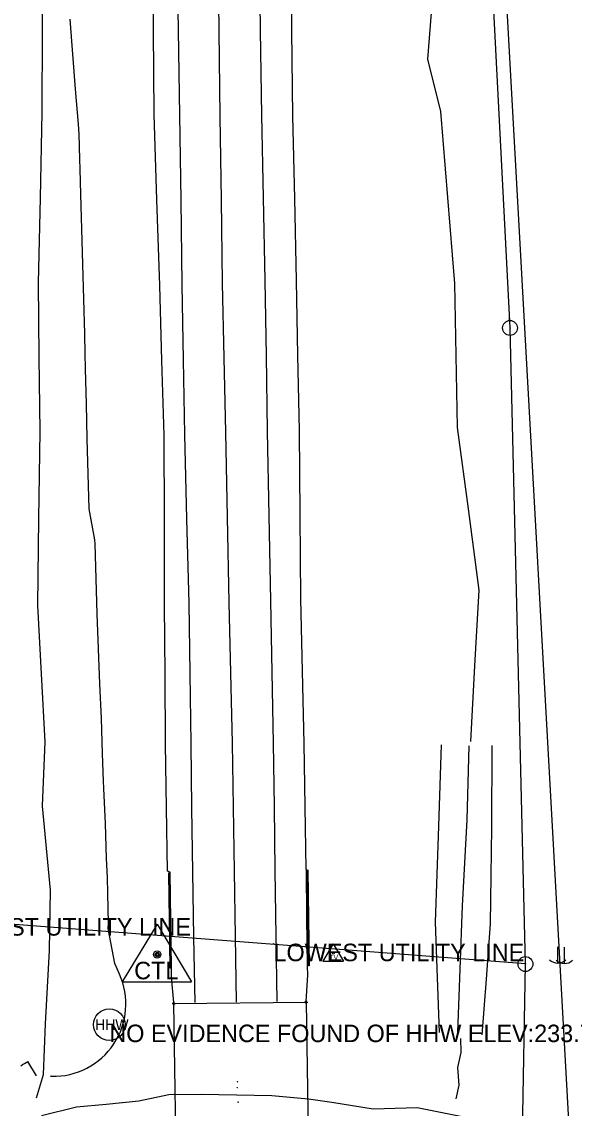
# Model space of a CAD drawing. Extents: x 1674300 to 1677920, y 225056 to 231852.
# Drawn here: x 1677397.6 to 1677555.6, y 229147 to 229457.6 of the extents above; entities that cross this region are included whole.
import ezdxf

# ---------------------------------------------------------------- set-up
doc = ezdxf.new("R2010")
doc.units = 0
for name, color, linetype in [('R_Proposed Const Limits_Cut', 7, 'Continuous'), ('R_Proposed Const Limits_Fill', 7, 'Continuous'), ('S_BRIDGE', 7, 'Continuous'), ('S_DITCHLINE', 7, 'Continuous'), ('S_EDGE_CONCRETE', 7, 'Continuous'), ('S_EDGE_PAVEMENT', 7, 'Continuous'), ('S_ELECTRIC_UTILITIES', 7, 'Continuous'), ('S_ELECTRIC_UTILITIES_ANNOT', 7, 'Continuous'), ('S_EXIST_ROW', 7, 'Continuous'), ('S_HIST_HIGH_WATER', 7, 'Continuous'), ('S_HIST_HIGH_WATER_ANNOT', 7, 'Continuous'), ('S_MSC_PT_SYM', 7, 'Continuous'), ('S_PAVEMENT_CROWN', 7, 'Continuous'), ('S_PRIMARY_CTL', 7, 'Continuous'), ('S_SECONDARY_CTL', 7, 'Continuous'), ('S_SHOULDER', 7, 'Continuous'), ('S_STR_PT_SYM', 7, 'Continuous'), ('S_STREAM', 7, 'Continuous'), ('S_UTILITY_POLE', 7, 'Continuous'), ('S_UTL_PT_SYM', 7, 'Continuous')]:
    doc.layers.add(name, color=color, linetype=linetype)

msp = doc.modelspace()

# ---------------------------------------------------------------- linework, layer by layer
at = {"layer": 'R_Proposed Const Limits_Cut'}
msp.add_lwpolyline([(1677397.4, 229159.19), (1677397.9, 229159.51), (1677398.39, 229159.82), (1677399.38, 229160.45)], dxfattribs=at)
at = {"layer": 'R_Proposed Const Limits_Fill'}
for p, q in [((1677401.84, 229156.28), (1677399.38, 229160.45)), ((1677406.18, 229156.17), (1677405.84, 229156.18))]:
    msp.add_line(p, q, dxfattribs=at)
msp.add_lwpolyline([(1677425.59, 229185.41), (1677424.21, 229188.45), (1677422.39, 229198.42), (1677422.41, 229199.98), (1677422.23, 229208.42), (1677422.12, 229212.97), (1677421.92, 229218.42), (1677421.54, 229228.42), (1677421.13, 229238.41), (1677421.04, 229240.56), (1677420.76, 229248.41), (1677420.41, 229258.4), (1677420.01, 229268.4), (1677419.61, 229278.39), (1677419.19, 229288.39), (1677418.88, 229298.38), (1677418.62, 229308.38), (1677418.58, 229309.52), (1677416.94, 229318.36), (1677416.67, 229328.36), (1677416.36, 229338.35), (1677416.12, 229348.35), (1677415.89, 229358.35), (1677415.78, 229362.8), (1677415.65, 229368.35), (1677415.39, 229378.34), (1677415.09, 229388.34), (1677414.81, 229398.34), (1677414.54, 229408.33), (1677414.35, 229415.48), (1677414.27, 229418.33), (1677414.07, 229425.48), (1677413.86, 229428.33), (1677413.04, 229438.32), (1677412.27, 229448.31), (1677411.5, 229458.3)], dxfattribs=at)
msp.add_arc((1677406.71, 229176.88), 20.71, 268.5476, 24.3154, dxfattribs=at)
at = {"layer": 'S_BRIDGE'}
for p, q in [((1677441.12, 229176.97), (1677478.98, 229177.38)), ((1677441.95, 229122.22), (1677441.12, 229176.97)), ((1677478.98, 229177.38), (1677479.86, 229122.68))]:
    msp.add_line(p, q, dxfattribs=at)
at = {"layer": 'S_DITCHLINE'}
for points in [[(1677401.81, 229150.07), (1677403.83, 229156.72), (1677404.42, 229171.13), (1677405.53, 229192.17), (1677405.88, 229209.42), (1677403.57, 229233.42), (1677404.29, 229251.75), (1677403.25, 229271.24), (1677402.21, 229290.73), (1677402.54, 229315.6), (1677402.86, 229340.46), (1677402.63, 229361.7), (1677402.41, 229382.95), (1677402.96, 229407.28), (1677403.51, 229431.62), (1677403.55, 229454.93), (1677403.6, 229478.23)], [(1677526.01, 229251.88), (1677527.22, 229273.51), (1677528.43, 229295.14), (1677525.35, 229318.39), (1677522.27, 229341.64), (1677521.88, 229362.2), (1677521.5, 229382.77), (1677519.49, 229407.37), (1677517.49, 229431.97), (1677513.78, 229446.92), (1677515.05, 229463.87)], [(1677525.45, 229250.61), (1677524.91, 229229.46), (1677523.57, 229204.88), (1677522.91, 229186.82), (1677522.26, 229168.76)]]:
    msp.add_lwpolyline(points, dxfattribs=at)
at = {"layer": 'S_EDGE_CONCRETE'}
for points in [[(1677517.07, 229168.73), (1677516.5, 229184.46), (1677515.92, 229200.19), (1677516.43, 229213.95), (1677516.93, 229227.7), (1677517.71, 229250.95)], [(1677529.33, 229168.07), (1677530.51, 229183.92), (1677531.7, 229199.76), (1677531.88, 229213.54), (1677532.07, 229227.32), (1677532.16, 229250.74)]]:
    msp.add_lwpolyline(points, dxfattribs=at)
for points in [[(1677439.61, 229214.28), (1677439.8, 229200.76), (1677439.99, 229187.23), (1677440.28, 229187.2), (1677440.08, 229200.79), (1677439.88, 229214.37)], [(1677479.45, 229215.12), (1677479.64, 229201.42), (1677479.83, 229187.73), (1677479.6, 229187.71), (1677479.42, 229201.44), (1677479.25, 229215.18)]]:
    msp.add_lwpolyline(points, close=True, dxfattribs=at)
at = {"layer": 'S_EDGE_PAVEMENT'}
for points in [[(1677447.19, 229177.27), (1677446.89, 229195.92), (1677446.59, 229214.57), (1677446.32, 229232.94), (1677446.04, 229251.31), (1677445.77, 229271.34), (1677445.49, 229291.37), (1677444.87, 229315.49), (1677444.24, 229339.62), (1677443.88, 229360.99), (1677443.52, 229382.36), (1677443.19, 229406.6), (1677442.86, 229430.84), (1677442.45, 229455.05), (1677442.04, 229479.26)], [(1677470.66, 229177.52), (1677470.39, 229196.28), (1677470.12, 229215.03), (1677469.88, 229233.21), (1677469.64, 229251.38), (1677469.24, 229271.73), (1677468.83, 229292.08), (1677468.37, 229316.34), (1677467.9, 229340.59), (1677467.59, 229362.11), (1677467.27, 229383.62), (1677466.77, 229407.23), (1677466.27, 229430.84), (1677465.93, 229455.12), (1677465.6, 229479.4)]]:
    msp.add_lwpolyline(points, dxfattribs=at)
at = {"layer": 'S_ELECTRIC_UTILITIES'}
for p, q in [((1677537.26, 229370.07), (1677525.77, 229595.69)), ((1677541.67, 229188.26), (1677537.26, 229370.07)), ((1677541.68, 229188.35), (1677278.13, 229208.63)), ((1677537.01, 228935.14), (1677541.67, 229188.26))]:
    msp.add_line(p, q, dxfattribs=at)
at = {"layer": 'S_EXIST_ROW'}
msp.add_line((1677555.5, 229117.02), (1677521.25, 229735.57), dxfattribs=at)
at = {"layer": 'S_HIST_HIGH_WATER'}
msp.add_circle((1677422.69, 229170.95), 4.5, dxfattribs=at)
at = {"layer": 'S_MSC_PT_SYM'}
for points in [[(1677469.62, 229194.08), (1677469.62, 229194.13), (1677469.62, 229194.08), (1677469.57, 229194.08), (1677469.62, 229194.08), (1677469.62, 229194.03), (1677469.62, 229194.08), (1677469.67, 229194.08)], [(1677459.3, 229154.61), (1677459.3, 229154.66), (1677459.3, 229154.61), (1677459.25, 229154.61), (1677459.3, 229154.61), (1677459.3, 229154.56), (1677459.3, 229154.61), (1677459.35, 229154.61)], [(1677459.27, 229153.01), (1677459.27, 229153.06), (1677459.27, 229153.01), (1677459.22, 229153.01), (1677459.27, 229153.01), (1677459.27, 229152.96), (1677459.27, 229153.01), (1677459.32, 229153.01)], [(1677459.52, 229148.81), (1677459.52, 229148.86), (1677459.52, 229148.81), (1677459.47, 229148.81), (1677459.52, 229148.81), (1677459.52, 229148.76), (1677459.52, 229148.81), (1677459.57, 229148.81)]]:
    msp.add_lwpolyline(points, dxfattribs=at)
at = {"layer": 'S_PAVEMENT_CROWN'}
msp.add_lwpolyline([(1677459.03, 229177.41), (1677458.76, 229196.1), (1677458.49, 229214.8), (1677458.18, 229233.1), (1677457.86, 229251.4), (1677457.39, 229271.52), (1677456.91, 229291.64), (1677456.47, 229315.95), (1677456.03, 229340.26), (1677455.53, 229361.57), (1677455.03, 229382.88), (1677454.71, 229406.68), (1677454.39, 229430.48), (1677454.11, 229454.96), (1677453.84, 229479.45)], dxfattribs=at)
at = {"layer": 'S_PRIMARY_CTL'}
for p, q in [((1677436.38, 229199.68), (1677426.35, 229183.17)), ((1677436.38, 229199.68), (1677446.2, 229183.17)), ((1677426.35, 229183.17), (1677446.2, 229183.17))]:
    msp.add_line(p, q, dxfattribs=at)
for radius in [1.04, 0.609, 0.344]:
    msp.add_circle((1677436.38, 229190.98), radius, dxfattribs=at)
at = {"layer": 'S_SECONDARY_CTL'}
for p, q in [((1677486.71, 229194.07), (1677483.7, 229189.11)), ((1677486.71, 229194.07), (1677489.66, 229189.11)), ((1677483.7, 229189.11), (1677489.66, 229189.11))]:
    msp.add_line(p, q, dxfattribs=at)
for radius in [0.311, 0.183, 0.103]:
    msp.add_circle((1677486.71, 229191.46), radius, dxfattribs=at)
at = {"layer": 'S_SHOULDER'}
for points in [[(1677440.09, 229214.52), (1677439.33, 229214.78), (1677439.05, 229232.96), (1677438.77, 229251.14), (1677438.61, 229271.03), (1677438.45, 229290.93), (1677438.42, 229315.16), (1677438.38, 229339.39), (1677437.73, 229360.81), (1677437.09, 229382.22), (1677436.3, 229406.69), (1677435.52, 229431.17), (1677435.32, 229455.13), (1677435.12, 229479.1)], [(1677479.01, 229215.37), (1677478.71, 229233.34), (1677478.41, 229251.31), (1677477.93, 229271.97), (1677477.44, 229292.63), (1677477.23, 229316.68), (1677477.02, 229340.72), (1677476.63, 229362.16), (1677476.23, 229383.6), (1677475.68, 229407.08), (1677475.14, 229430.56), (1677474.9, 229455.1), (1677474.67, 229479.64)], [(1677441.13, 229177.25), (1677440.48, 229184.47), (1677440.48, 229187.18), (1677440.28, 229200.83), (1677440.08, 229214.48)], [(1677479, 229177.6), (1677479.4, 229185.05), (1677479.36, 229187.71), (1677479.19, 229201.54), (1677479.02, 229215.37)]]:
    msp.add_lwpolyline(points, dxfattribs=at)
at = {"layer": 'S_STR_PT_SYM'}
for points in [[(1677441.12, 229176.97), (1677441.12, 229177.47), (1677441.12, 229176.97), (1677440.62, 229176.97), (1677441.12, 229176.97), (1677441.12, 229176.47), (1677441.12, 229176.97), (1677441.62, 229176.97)], [(1677478.98, 229177.38), (1677478.98, 229177.88), (1677478.98, 229177.38), (1677478.48, 229177.38), (1677478.98, 229177.38), (1677478.98, 229176.88), (1677478.98, 229177.38), (1677479.48, 229177.38)]]:
    msp.add_lwpolyline(points, dxfattribs=at)
at = {"layer": 'S_STREAM'}
for points in [[(1677523.11, 229166.98), (1677523.18, 229162.94), (1677522.26, 229158.65), (1677522.58, 229153.61), (1677521.72, 229149.78)], [(1677527.43, 229143.82), (1677510.66, 229147.15), (1677498.12, 229146.82), (1677486.33, 229148.7), (1677479.59, 229149.67), (1677469.13, 229150.63), (1677448.9, 229150.99), (1677439.66, 229150.9), (1677431.13, 229149.09), (1677421.74, 229148.09), (1677413.29, 229147.37), (1677403.31, 229144.91)]]:
    msp.add_lwpolyline(points, dxfattribs=at)
at = {"layer": 'S_UTILITY_POLE'}
for p, q in [((1677537.13, 229372.21), (1677537.13, 229374.32)), ((1677541.54, 229190.4), (1677541.54, 229192.51)), ((1677550.83, 229193.23), (1677550.83, 229188.5)), ((1677552.73, 229193.13), (1677552.73, 229188.41))]:
    msp.add_line(p, q, dxfattribs=at)
for centre in [(1677537.26, 229370.07), (1677541.67, 229188.26)]:
    msp.add_circle(centre, 2.13, dxfattribs=at)
for centre in [(1677550.89, 229191.93), (1677552.79, 229191.83)]:
    msp.add_arc(centre, 3.41, 226.3972, 313.6028, dxfattribs=at)
at = {"layer": 'S_UTL_PT_SYM'}
for points in [[(1677537.26, 229370.07), (1677537.26, 229370.12), (1677537.26, 229370.07), (1677537.21, 229370.07), (1677537.26, 229370.07), (1677537.26, 229370.02), (1677537.26, 229370.07), (1677537.31, 229370.07)], [(1677469.62, 229194.08), (1677469.62, 229194.13), (1677469.62, 229194.08), (1677469.57, 229194.08), (1677469.62, 229194.08), (1677469.62, 229194.03), (1677469.62, 229194.08), (1677469.67, 229194.08)], [(1677541.67, 229188.26), (1677541.67, 229188.31), (1677541.67, 229188.26), (1677541.62, 229188.26), (1677541.67, 229188.26), (1677541.67, 229188.21), (1677541.67, 229188.26), (1677541.72, 229188.26)], [(1677541.68, 229188.35), (1677541.68, 229188.4), (1677541.68, 229188.35), (1677541.63, 229188.35), (1677541.68, 229188.35), (1677541.68, 229188.3), (1677541.68, 229188.35), (1677541.73, 229188.35)]]:
    msp.add_lwpolyline(points, dxfattribs=at)

# ---------------------------------------------------------------- texts
at = {"layer": 'S_ELECTRIC_UTILITIES_ANNOT'}
for p in [(1677374.33, 229196.39), (1677469.62, 229189.08)]:
    msp.add_text('LOWEST UTILITY LINE', height=5, rotation=360, dxfattribs=at).set_placement(p)
at = {"layer": 'S_HIST_HIGH_WATER'}
msp.add_text('HHW', height=3, rotation=360, dxfattribs=at).set_placement((1677418.6, 229169.45))
at = {"layer": 'S_HIST_HIGH_WATER_ANNOT'}
msp.add_text('NO EVIDENCE FOUND OF HHW ELEV:233.79', height=5, rotation=360, dxfattribs=at).set_placement((1677422.69, 229165.95))
at = {"layer": 'S_PRIMARY_CTL'}
msp.add_text('CTL', height=5, rotation=360, dxfattribs=at).set_placement((1677429.79, 229183.91))
at = {"layer": 'S_SECONDARY_CTL'}
msp.add_text('TV', height=1.5, rotation=360, dxfattribs=at).set_placement((1677485.51, 229189.45))

doc.saveas('drawing.dxf')
